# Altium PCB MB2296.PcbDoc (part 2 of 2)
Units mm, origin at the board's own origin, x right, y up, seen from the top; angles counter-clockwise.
Board outline 43 x 47.02 mm, 4 copper layers (Top Layer, Internal 1, Internal 2, Bottom Layer), stack 1.565 mm thick; 91 components, 90 nets, 355 pads, 438 vias.
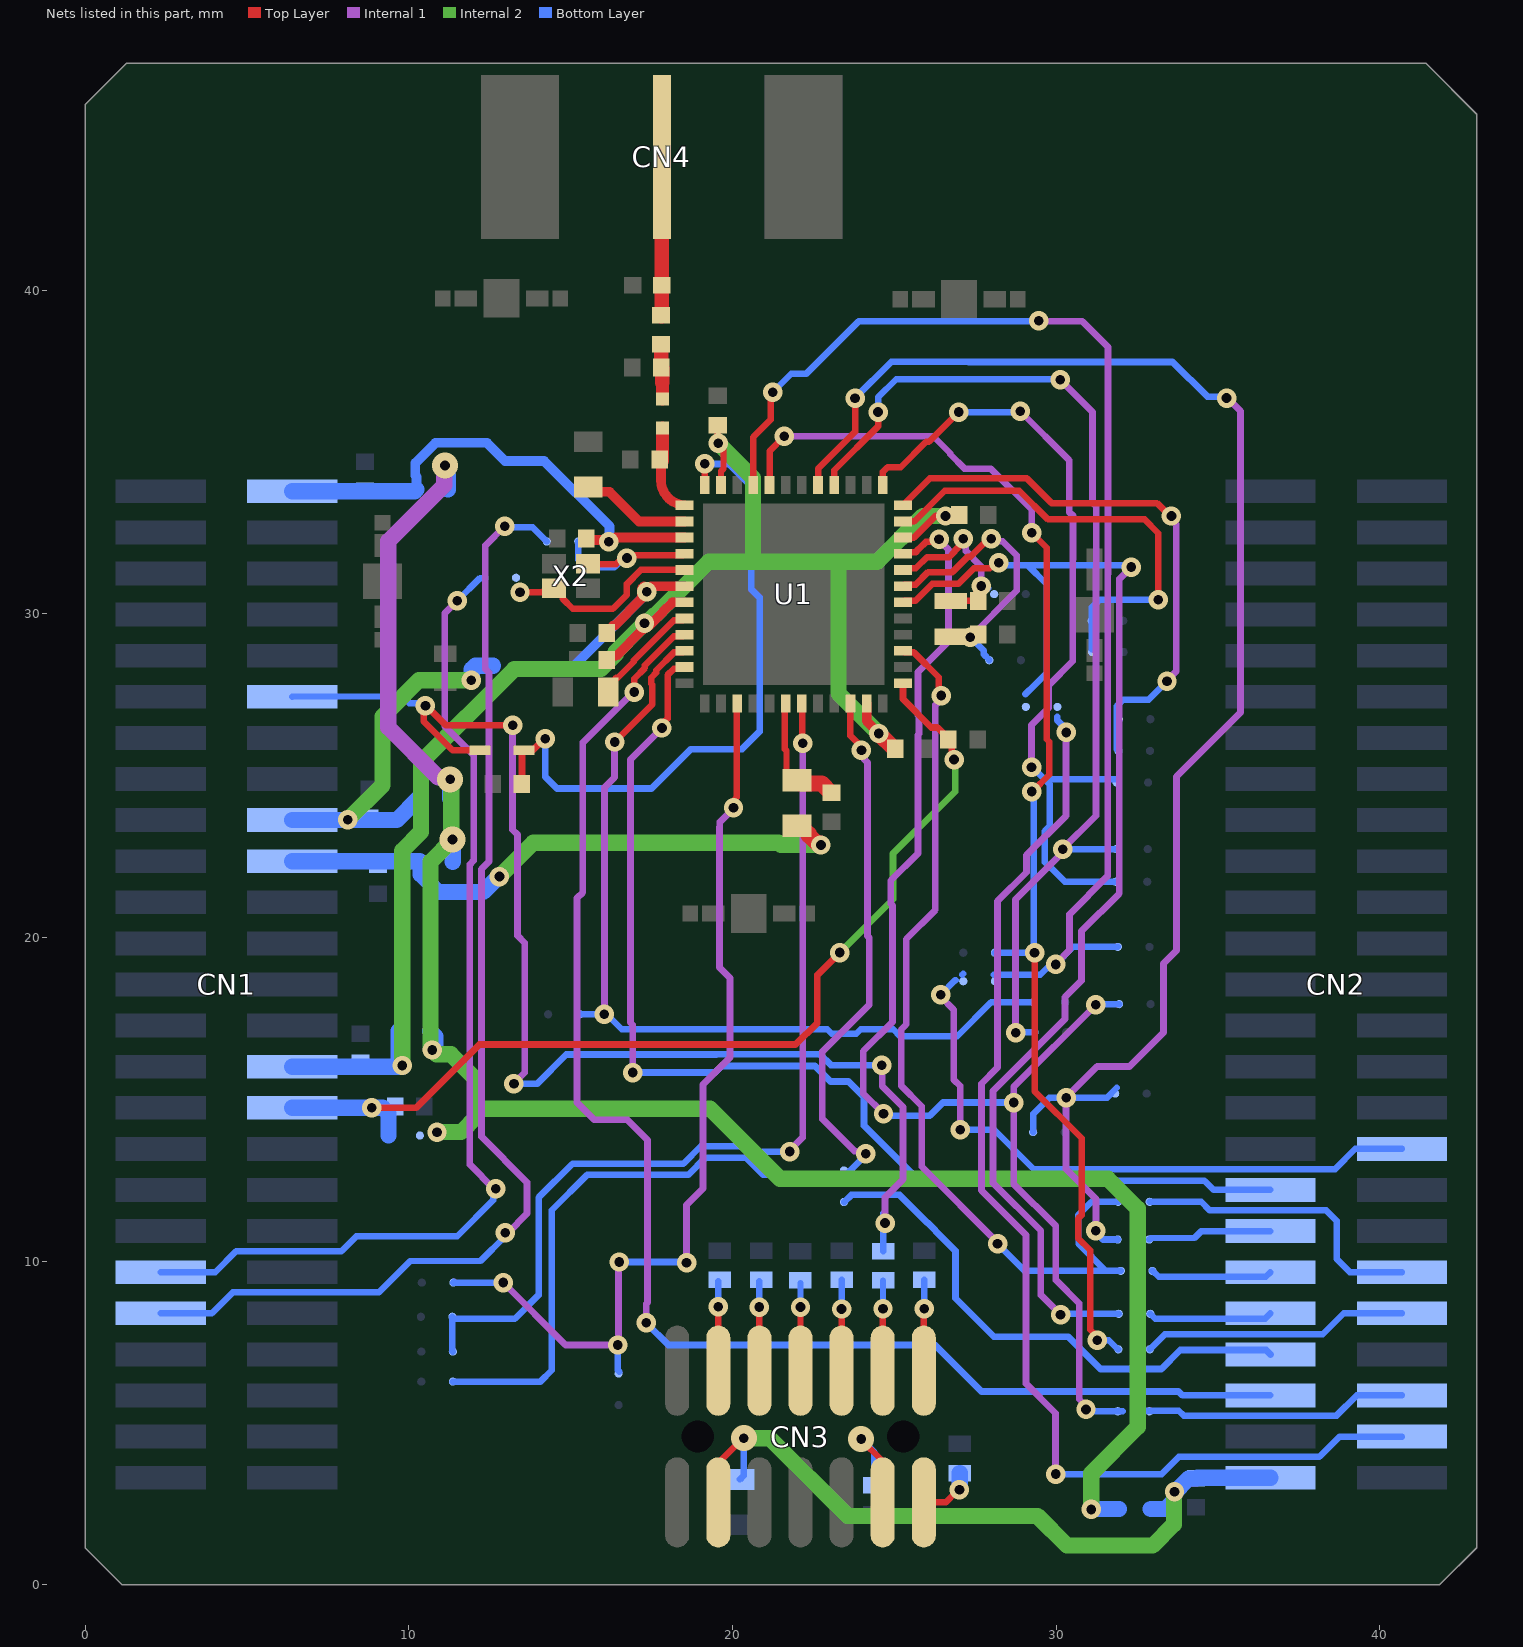
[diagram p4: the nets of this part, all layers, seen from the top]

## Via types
v1: diameter 0.6, hole 0.3, Top Layer to Bottom Layer, tented both sides, 433 vias
v2: diameter 0.8, hole 0.3, Top Layer to Bottom Layer, tented both sides, 5 vias

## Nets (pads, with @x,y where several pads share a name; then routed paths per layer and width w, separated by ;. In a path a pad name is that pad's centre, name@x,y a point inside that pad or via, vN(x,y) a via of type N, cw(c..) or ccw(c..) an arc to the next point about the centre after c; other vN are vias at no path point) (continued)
GPIO46: CN2.34 SB32.2 | length 19.6
  Internal 1 w0.21: v1(26.436,18.235) 26.436,18.17 26.835,17.771 26.835,15.612 27.039,15.408 v1(27.039,14.062)
  Bottom Layer w0.2: v1(26.436,18.235) 26.886,18.685 26.894,18.685 ; v1@27.039,14.163 v1(27.039,14.062) 28.086,14.062 29.305,12.843 38.621,12.843 39.246,13.468 CN2.34@40.688,13.468 ; 27.094,18.845 27.13,18.88
GPIO47: CN2.35 U1.47 | length 35.3
  Top Layer w0.2: v1(17.82,26.474) 17.82,26.582 17.995,26.757 17.995,28.112 18.191,28.308 18.47,28.308 U1.47@18.52,28.358
  Internal 1 w0.21: v1(16.916,15.826) 16.916,17.304 16.845,17.375 16.845,25.499 v1(17.82,26.474)
  Bottom Layer w0.2: 27.586,12.487 34.582,12.487 34.871,12.198 CN2.35@36.624,12.198
  Bottom Layer w0.21: v1(16.916,15.826) 19.463,15.826 19.668,16.031 22.553,16.031 23.033,15.55 23.581,15.55 24.061,15.07 24.061,14.184 25.758,12.487 27.586,12.487
GPIO49: CN2.37 SB29.1 | length 3.9
  Bottom Layer w0.2: SB29.1@32.877,10.668 32.892,10.668 32.938,10.715 34.276,10.715 34.49,10.928 CN2.37@36.624,10.928
GPIO50: CN2.39 SB12.1 | length 3.8
  Bottom Layer w0.2: SB12.1@32.975,9.698 32.99,9.698 33.173,9.514 36.48,9.514 CN2.39@36.624,9.658
GPIO51: CN2.40 SB15.2 | length 9.4
  Bottom Layer w0.2: SB15.2@32.889,11.832 34.481,11.832 34.741,11.573 38.342,11.573 38.672,11.243 38.672,10.066 39.08,9.658 CN2.40@40.688,9.658
GPIO52: CN2.41 SB16.2 | length 3.8
  Bottom Layer w0.2: SB16.2@32.91,8.371 33.061,8.22 36.456,8.22 CN2.41@36.624,8.388
GPIO53: CN2.42 SB18.2 | length 8.3
  Bottom Layer w0.2: SB18.2@32.898,7.274 33.362,7.738 38.24,7.738 38.891,8.388 CN2.42@40.688,8.388
GPIO54: CN2.43 SB8.1 | length 16.7
  Bottom Layer w0.21: SB8.1@23.454,11.827 23.676,12.048 24.305,12.048 25.158,12.048 26.01,11.195 26.021,11.195 26.527,10.688 26.527,10.678 26.887,10.318 26.887,8.852 28.074,7.666 30.374,7.666 31.374,6.666 33.251,6.666 33.836,7.251 36.492,7.251 CN2.43@36.624,7.118
GPIO55: CN2.45 U1.45 | length 44.6
  Top Layer w0.2: v1(16.967,27.584) 16.963,27.589 16.963,27.999 17.295,28.331 17.295,28.412 18.191,29.308 18.47,29.308 U1.45@18.52,29.358
  Internal 1 w0.21: v1(16.967,27.584) 16.935,27.584 15.374,26.023 15.374,21.397 15.196,21.219 15.196,14.906 15.736,14.367 16.753,14.367 17.374,13.747 17.374,8.718 17.336,8.68 v1(17.336,8.093)
  Bottom Layer w0.2: 33.782,5.972 33.906,5.848 CN2.45@36.624,5.848
  Bottom Layer w0.21: v1(17.336,8.093) 18.016,7.413 26.253,7.413 27.694,5.972 33.782,5.972
GPIO56: CN2.46 SB34.2 | length 8.4
  Bottom Layer w0.2: 32.655,5.377 32.885,5.377 32.892,5.37 32.91,5.37 32.917,5.377 33.79,5.377 33.941,5.226 38.667,5.226 39.289,5.848 CN2.46@40.688,5.848
GPIO57: CN2.48 SB42.2 | length 36.7
  Internal 1 w0.21: v1(29.985,3.42) 29.985,5.299 29.071,6.214 29.071,10.811 27.694,12.188 27.694,15.482 28.191,15.979 28.191,21.123 29.085,22.016 29.085,22.543 30.302,23.761 30.302,26.329 v1(30.31,26.337)
  Bottom Layer w0.2: v1(29.985,3.42) 33.262,3.42 33.795,3.953 38.138,3.953 38.764,4.578 CN2.48@40.688,4.578
  Bottom Layer w0.21: 30.033,26.823 30.033,26.72 30.31,26.442 v1(30.31,26.337)
NetC7_2: C7.2 D1.1 U1.36 | length 20.8
  Top Layer w0.21: C7.2@13.492,24.745 13.492,25.722 D1.1@13.554,25.784 13.827,25.784 v1@14.212,26.169 ; v1(14.212,26.145) v1@14.212,26.169 ; v1@14.332,26.289 v1@14.212,26.169 ; U1.36@19.145,33.983 v1(19.145,34.636)
  Bottom Layer w0.21: v1(14.212,26.145) 14.212,24.969 14.579,24.602 17.499,24.602 18.717,25.82 20.293,25.82 20.841,26.368 20.841,30.505 20.578,30.768 20.578,33.952 19.894,34.636 v1(19.145,34.636)
NetC8_2: C8.2 SB38.1 U1.19 X1.2 | length 9.4
  Top Layer w0.2: U1.19@25.27,30.858 25.32,30.908 25.661,30.908 26.044,31.292 26.797,31.292 27.277,31.772 27.362,31.772 27.912,32.322 v1(28.001,32.322) ; v1(27.347,29.283) 27.512,29.283 C8.2@27.592,29.362
  Top Layer w0.21: X1.2@26.814,29.295 26.959,29.15 C8.2@27.461,29.15
  Internal 1 w0.2: v1(27.347,29.283) 28.779,30.715 28.779,31.813 28.347,32.245 28.077,32.245 v1(28.001,32.322)
  Bottom Layer w0.2: v1(27.347,29.283) 27.771,28.858 27.771,28.749 27.936,28.583 SB38.1@27.936,28.569
NetC9_2: C9.2 SB37.1 U1.20 X1.1 | length 5.8
  Top Layer w0.2: U1.20@25.27,31.358 25.32,31.408 25.666,31.408 26.011,31.753 26.697,31.753 26.847,31.902 26.847,31.926 27.134,32.214 v1(27.134,32.322) ; X1.1@26.644,30.395 26.648,30.399 C9.2@27.576,30.399 ; C9.2@27.576,30.616 C9.2@27.549,30.643 ; C9.2@27.592,30.404 27.587,30.399 C9.2@27.576,30.399 ; v1(27.686,30.861) 27.549,30.724 C9.2@27.549,30.643 ; C9.2@27.549,30.643 27.549,30.426 C9.2@27.576,30.399
  Internal 1 w0.21: v1(27.134,32.322) 27.209,32.247 27.209,31.948 27.686,31.471 v1(27.686,30.861)
  Bottom Layer w0.2: v1(27.686,30.861) 27.747,30.8 v1@27.899,30.8
NetC11_2: C11.2 U1.38 | length 3.4
  Top Layer w0.3: C11.2@15.545,33.92 15.693,33.772 16.198,33.772 17.112,32.858 U1.38@18.52,32.858
NetC12_2: C12.2 L1.1 U1.37 | length 2.9
  Top Layer w0.2: L1.1@17.785,35.7 L1.1@17.831,35.745 ; C12.2@17.789,34.731 C12.2@17.831,34.731
  Top Layer w0.3: L1.1@17.785,35.7 L1.1@17.789,35.696 ; C12.2@17.789,34.731 17.789,34.131 ccw(c18.563,34.131) U1.37@18.52,33.358
  Top Layer w0.4: C12.2@17.831,34.731 L1.1@17.831,35.745
NetC13_2: C13.2 L1.2 L2.1 | length 1.7
  Top Layer w0.4: L1.2@17.831,36.645 17.831,37.15
  Top Layer w0.45: L2.1@17.797,38.325 C13.2@17.798,37.617 17.828,37.587 17.828,37.371 17.831,37.368 17.831,37.15
NetC14_2: C14.2 CN4.1 L2.2 | length 4.9
  Top Layer w0.45: L2.2@17.796,39.226 L2.2@17.808,39.237 ; L2.2@17.811,39.231 C14.2@17.811,40.152 ; C14.2@17.816,40.157 CN4.1@17.816,44.118
  Top Layer w0.5: L2.2@17.808,39.231 L2.2@17.811,39.231 ; C14.2@17.811,40.152 C14.2@17.816,40.157 ; CN4.1@17.816,44.118 CN4.1@17.819,44.12
NetC15_1: C15.1 SB6.2 U1.42 | length 8
  Top Layer w0.3: C15.1@16.123,29.444 16.318,29.639 16.362,29.639 17.193,30.469 17.193,30.781 17.264,30.853 17.346,30.772 17.389,30.772 17.475,30.858 U1.42@18.52,30.858
  Bottom Layer w0.3: SB6.2@13.571,28.401 15.114,28.401 17.348,30.635 v1(17.348,30.683)
NetC20_2: C20.2 L3.2 U1.6 | length 3.8
  Top Layer w0.2: U1.6@21.645,27.233 21.619,27.207 21.619,25.821 21.669,25.771 21.669,25.109 21.919,24.859 L3.2@21.995,24.859
  Top Layer w0.5: L3.2@21.995,24.859 22.095,24.759 22.758,24.759 23.038,24.478 C20.2@23.063,24.478
NetC29_1: C29.1 U1.44 | length 3.4
  Top Layer w0.2: C29.1@16.159,27.586 16.164,27.581 16.359,27.776 16.359,27.978 16.402,28.021 16.442,28.021 16.466,28.045 16.945,28.524 16.945,28.562 18.191,29.808 18.47,29.808 U1.44@18.52,29.858
NetCN3_4: CN3.4 R2.1 | length 2.8
  Top Layer w0.2: CN3.4@19.561,6.614 v1(19.561,8.589) v1@19.561,8.639
  Bottom Layer w0.2: v1(19.561,8.589) R2.1@19.561,9.384
NetCN3_6: CN3.6 R3.1 | length 2.8
  Top Layer w0.2: CN3.6@20.831,6.614 v1(20.831,8.579)
  Bottom Layer w0.2: v1(20.831,8.579) R3.1@20.831,9.372
NetCN3_8: CN3.8 R4.1 | length 2.7
  Top Layer w0.2: CN3.8@22.101,6.614 v1(22.101,8.579)
  Bottom Layer w0.2: v1(22.101,8.579) R4.1@22.101,9.31
NetCN3_10: CN3.10 R5.1 | length 2.8
  Top Layer w0.2: CN3.10@23.371,6.614 v1(23.371,8.519)
  Bottom Layer w0.2: v1(23.371,8.519) R5.1@23.371,9.423
NetCN3_11: CN3.11 R6.2 | length 3.9
  Top Layer w0.2: v2(23.976,4.504) 23.951,4.504 24.641,3.814 CN3.11@24.641,2.544
  Bottom Layer w0.2: v2(23.976,4.504) 24.386,4.094 R6.2@24.386,3.081
NetCN3_12: CN3.12 R7.1 | length 2.8
  Top Layer w0.2: CN3.12@24.641,6.614 24.641,8.519 v1(24.651,8.529)
  Bottom Layer w0.2: v1(24.651,8.529) R7.1@24.651,9.396
NetCN3_13: CN3.13 R9.2 | length 1.6
  Top Layer w0.2: CN3.13@25.911,2.544 26.591,2.544 v1@26.901,2.854
  Bottom Layer w0.5: v1@27.024,2.947 R9.2@27.024,3.45
  other v1: 27.013,2.937
NetCN3_14: CN3.14 R8.1 | length 2.8
  Top Layer w0.2: CN3.14@25.911,6.614 25.911,8.539 25.921,8.529 v1(25.926,8.529)
  Bottom Layer w0.2: v1(25.926,8.529) R8.1@25.926,9.424
NetSB1_1: SB1.1 SB2.1 SB3.1 SB4.1 SB5.1 SB43.1 | length 59.6
  Internal 1 w0.5: v2(11.115,34.585) 11.093,34.563 11.093,33.981 9.36,32.249 9.36,26.494 10.909,24.945 11.218,24.945 v2(11.275,24.888)
  Internal 2 w0.5: v1(10.87,13.983) 10.875,13.988 11.612,13.988 12.102,14.477 12.102,14.709 ; v2(11.275,24.888) 11.312,24.852 11.312,23.072 v2@11.352,23.032 ; v2(11.348,23.028) 11.348,23.022 10.671,22.344 10.671,16.573 10.852,16.391 11.299,16.391 12.102,15.589 12.102,14.709 ; v1(31.087,2.327) 31.087,3.439 32.525,4.877 32.525,11.624 31.601,12.548 21.468,12.548 19.307,14.709 12.102,14.709
  Bottom Layer w0.5: SB4.1@10.651,17.107 10.814,16.945 10.814,16.591 10.745,16.523 v1(10.721,16.523) ; v2(11.115,34.585) 11.172,34.528 11.172,34.316 11.214,34.274 SB2.1@11.214,33.846 ; SB3.1@11.269,24.295 11.269,24.882 v2(11.275,24.888) ; v2(11.348,23.028) 11.355,23.022 SB1.1@11.355,22.342 ; v1(31.087,2.327) 31.103,2.343 SB5.1@31.947,2.343
NetSB7_1: SB7.1 SB11.1 U1.24 | length 17.7
  Top Layer w0.2: U1.24@25.27,33.358 26.099,34.187 29.098,34.187 29.859,33.426 33.116,33.426 33.517,33.025 v1(33.563,33.025)
  Internal 1 w0.21: v1(33.426,27.915) 33.426,27.944 33.715,28.233 33.715,32.768 33.563,32.919 v1(33.563,33.025)
  Bottom Layer w0.2: SB11.1@31.878,26.746 31.878,25.817 SB7.1@31.928,25.767 ; SB11.1@31.914,26.746 31.929,26.76 31.929,26.771 31.878,26.821 31.878,27.151 32.073,27.346 32.858,27.346 v1(33.426,27.915)
NetSB8_2: SB8.2 SB9.2 U1.10 | length 34.5
  Top Layer w0.2: U1.10@23.645,27.233 23.645,26.232 23.985,25.891 v1(23.985,25.783)
  Internal 1 w0.21: 23.673,17.377 22.776,16.48 22.776,14.391 23.77,13.397 23.942,13.397 24.025,13.314 v1@24.025,13.265 ; 23.674,17.377 24.228,17.931 24.228,19.991 24.17,20.048 24.17,25.406 24.06,25.516 24.06,25.709 v1(23.985,25.783)
  Bottom Layer w0.2: SB9.2@11.359,6.277 14.067,6.277 14.415,6.625 14.415,11.573 15.505,12.663 18.629,12.663 19.165,13.199 20.421,13.199 20.957,12.663 23.496,12.663 24.155,13.322 v1(24.122,13.322)
NetSB10_1: SB10.1 SB13.1 U1.23 | length 14.3
  Top Layer w0.2: U1.23@25.27,32.858 25.613,32.858 26.56,33.805 28.865,33.805 29.751,32.92 32.736,32.92 33.16,32.496 v1(33.16,30.437)
  Bottom Layer w0.2: SB10.1@31.102,28.905 31.102,29.7 31.105,29.704 31.105,30.2 31.343,30.437 v1(33.16,30.437)
NetSB12_2: SB12.2 SB15.1 U1.15 | length 28.4
  Top Layer w0.2: U1.15@25.27,28.858 25.32,28.808 25.607,28.808 26.377,28.039 26.377,27.553 v1(26.453,27.476)
  Internal 1 w0.2: v1(26.453,27.476) 26.453,27.368 26.271,27.186 26.271,20.852 25.37,19.951 25.37,17.313 25.21,17.152 25.21,15.425 25.846,14.789 25.846,12.922 28.191,10.577 v1(28.191,10.541)
  Bottom Layer w0.2: v1(28.191,10.541) 29.034,9.698 31.538,9.698 ; SB15.1@31.914,11.832 31.095,11.832 30.68,11.417 30.68,10.71 30.693,10.697 30.693,10.542 31.538,9.698 ; SB12.2@32,9.698 31.538,9.698
NetSB14_2: SB14.2 SB17.2 U1.7 | length 29.6
  Top Layer w0.21: U1.7@22.145,27.233 22.157,27.221 22.157,26.012 v1(22.169,26)
  Internal 1 w0.21: v1(21.768,13.386) 21.768,13.417 22.169,13.818 v1(22.169,26)
  Bottom Layer w0.2: SB17.2@11.345,8.28 11.339,8.274 SB17.2@11.339,8.221 ; SB14.2@11.359,7.205 11.339,7.224 SB17.2@11.339,8.221 ; v1(21.768,13.386) 20.729,13.386 20.566,13.549 19.02,13.549 18.484,13.013 15.057,13.013 14.008,11.964 14.008,8.952 13.278,8.221 SB17.2@11.339,8.221
NetSB16_1: SB16.1 SB42.1 U1.18 | length 39.4
  Top Layer w0.2: U1.18@25.27,30.358 25.32,30.408 25.656,30.408 26.174,30.926 26.973,30.926 27.46,31.413 27.949,31.413 28.121,31.585 v1(28.229,31.585)
  Internal 1 w0.21: v1(30.137,8.347) 29.528,8.957 29.528,10.938 28.054,12.412 28.054,15.256 30.277,17.48 30.277,18.156 30.788,18.666 30.788,20.199 31.955,21.366 31.955,31.08 v1(32.322,31.447)
  Bottom Layer w0.2: v1(28.229,31.585) 28.305,31.51 29.118,31.51 ; 29.325,27.79 29.709,28.175 29.709,30.918 29.118,31.51 ; v1@30.417,8.371 SB16.1@31.935,8.371 ; v1(32.322,31.447) 32.259,31.51 29.118,31.51
  Bottom Layer w0.21: 29.058,27.523 29.325,27.79
NetSB18_1: SB18.1 SB20.1 U1.32 | length 39.4
  Top Layer w0.2: U1.32@21.145,33.983 21.145,35.03 v1(21.602,35.487) ; v1(29.245,32.508) 29.709,32.044 29.709,26.129 29.791,26.047 29.791,25.032 29.269,24.509 v1(29.248,24.509) ; v1(29.335,19.531) 29.335,15.25 30.789,13.795 30.789,11.424 30.68,11.315 30.68,10.71 31.055,10.335 31.055,7.879 31.27,7.663 v1(31.27,7.555)
  Internal 1 w0.2: v1(21.602,35.487) 26.206,35.487 26.728,34.965 26.728,34.931 27.166,34.493 27.976,34.493 29.245,33.224 v1(29.245,32.508)
  Bottom Layer w0.2: SB20.1@28.108,19.531 v1(29.335,19.531) 29.303,19.562 29.303,24.454 v1(29.248,24.509) ; v1(31.27,7.555) 31.628,7.555 31.909,7.274 SB18.1@31.923,7.274
NetSB19_2: SB19.2 SB21.2 U1.3 | length 29.6
  Top Layer w0.2: v1(20.031,24.013) 20.108,24.09 20.108,24.305 20.133,24.33 20.133,27.221 U1.3@20.145,27.233
  Internal 1 w0.21: v1(12.916,9.338) 14.847,7.407 v1(16.452,7.407) 16.476,7.431 16.476,9.951 v1(16.498,9.973) ; v1(18.58,9.947) 18.58,11.736 19.085,12.24 19.085,15.457 19.92,16.293 19.92,18.753 19.598,19.075 19.598,23.41 19.607,23.419 19.607,23.568 20.031,23.992 v1(20.031,24.013)
  Bottom Layer w0.2: SB19.2@11.375,9.337 11.402,9.363 11.427,9.338 v1(12.916,9.338) ; v1(16.452,7.407) 16.452,6.632 SB21.2@16.506,6.578
  Bottom Layer w0.21: v1(16.498,9.973) 18.555,9.973 v1(18.58,9.947)
NetSB22_2: SB22.2 SB24.2 SB29.2 U1.29 | length 49
  Top Layer w0.2: U1.29@22.645,33.983 22.645,34.484 23.787,35.627 v1(23.787,36.668)
  Internal 1 w0.21: v1(31.23,10.938) 31.23,11.92 30.31,12.84 v1(30.31,15.053) 31.27,16.014 32.267,16.014 33.316,17.063 33.316,19.197 33.719,19.599 33.719,24.97 35.7,26.951 35.7,36.264 35.295,36.669 v1(35.269,36.669)
  Bottom Layer w0.2: v1(23.787,36.668) 24.906,37.787 27.29,37.787 ; SB22.2@29.291,13.988 29.291,14.549 29.794,15.053 v1(30.31,15.053) 31.574,15.053 31.876,15.354
  Bottom Layer w0.21: 27.29,37.787 33.599,37.787 34.673,36.713 35.225,36.713 v1(35.269,36.669) ; v1(31.23,10.938) 31.2,10.938 31.19,10.928 31.451,10.668 SB29.2@31.902,10.668
NetSB26_2: SB26.2 SB27.2 U1.28 | length 33.1
  Top Layer w0.2: U1.28@23.145,33.983 23.145,34.438 24.499,35.792 v1(24.499,36.236)
  Internal 1 w0.21: v1(28.749,17.053) 28.749,21.171 30.203,22.626 v1(30.203,22.731) 31.235,23.762 31.235,31.378 31.24,31.383 31.24,33.334 31.126,33.449 31.126,36.236 30.129,37.232 v1(30.125,37.232)
  Bottom Layer w0.2: v1(24.499,36.236) 24.499,36.694 25.057,37.252 30.105,37.252 v1(30.125,37.232) ; v1(28.749,17.053) 28.772,17.075 SB27.2@29.335,17.075 ; v1(30.203,22.731) SB26.2@31.858,22.731
NetSB28_2: SB28.2 SB30.2 U1.46 | length 27.3
  Top Layer w0.2: v1(16.358,26.041) 17.517,27.2 17.517,27.812 17.486,27.844 17.486,28.027 17.645,28.186 17.645,28.262 18.191,28.808 18.47,28.808 U1.46@18.52,28.858
  Internal 1 w0.21: v1@16.049,17.639 16.049,24.642 16.358,24.95 v1(16.358,26.041)
  Bottom Layer w0.2: v1(16.037,17.628) 16.118,17.628 16.581,17.165 22.925,17.165 23.067,17.022 23.821,17.022 23.964,17.165 24.964,17.165 25.178,16.951 26.943,16.951 27.992,18 SB28.2@29.307,18
  Bottom Layer w0.21: SB30.2@15.279,17.628 v1(16.037,17.628)
NetSB31_1: SB31.1 SB32.1 U1.33 | length 38.7
  Top Layer w0.2: U1.33@20.645,33.983 20.645,35.465 21.185,36.005 21.185,36.783 v1(21.247,36.846)
  Internal 1 w0.21: v1(29.464,39.062) 29.484,39.042 30.81,39.042 31.6,38.252 31.6,31.234 31.595,31.229 31.595,21.895 30.417,20.717 30.417,19.611 29.991,19.185 v1(29.991,19.168)
  Bottom Layer w0.2: v1(21.247,36.846) 21.758,37.356 21.815,37.414 22.272,37.414 23.634,38.776 ; 28.069,18.845 29.511,18.845 29.833,19.168 v1(29.991,19.168) 30.534,19.71 SB31.1@31.91,19.71
  Bottom Layer w0.21: 23.634,38.776 23.901,39.042 29.444,39.042 v1(29.464,39.062)
NetSB33_2: SB33.2 SB35.2 U1.25 | length 25.5
  Top Layer w0.2: U1.25@24.645,33.983 24.645,34.386 24.793,34.535 25.198,34.535 25.983,35.32 26.072,35.32 v1(26.988,36.236)
  Internal 1 w0.21: v1(28.893,36.262) 30.406,34.749 30.406,33.15 30.52,33.036 30.52,31.681 30.515,31.676 30.515,28.542 29.765,27.793 29.765,27.092 29.241,26.568 v1(29.241,25.259)
  Bottom Layer w0.2: v1(26.988,36.236) v1@28.918,36.236 ; v1(29.241,25.259) 29.275,25.259 29.642,24.893 ; SB35.2@31.842,21.723 30.273,21.723 29.787,22.209 29.771,22.209 29.653,22.326 29.653,23.288 29.798,23.433 29.798,24.737 29.642,24.893 ; SB33.2@31.852,24.893 29.642,24.893
NetSB34_1: SB34.1 SB36.1 U1.21 | length 41.2
  Top Layer w0.21: U1.21@25.27,31.858 25.315,31.903 25.653,31.903 25.753,32.003 25.755,32.003 25.981,32.229 26.31,32.229 v1(26.385,32.303)
  Internal 1 w0.21: v1(24.666,14.556) 24.041,15.18 24.041,16.486 24.948,17.393 24.948,20.993 24.89,21.051 24.89,21.755 25.735,22.599 25.735,26.262 25.766,26.294 25.766,26.837 25.735,26.869 25.735,28.204 26.673,29.143 26.673,31.985 26.385,32.274 v1(26.385,32.303) ; v1(30.925,5.417) 30.925,5.523 30.715,5.732 30.715,8.696 29.992,9.419 29.992,11.084 28.69,12.386 v1(28.69,14.9) 28.69,15.383 v1(31.23,17.923)
  Bottom Layer w0.2: v1(30.925,5.417) 30.983,5.359 SB34.1@31.91,5.359 32.064,5.359 ; v1(31.23,17.923) 31.248,17.941 SB36.1@31.946,17.941
  Bottom Layer w0.21: v1(24.666,14.556) 24.727,14.494 26.099,14.494 26.505,14.9 v1(28.69,14.9)
NetSB39_1: SB39.1 U1.41 X2.1 | length 6.2
  Top Layer w0.2: v1(13.434,30.673) 14.091,30.673 ; X2.1@14.141,30.678 14.364,30.678 X2.1@14.484,30.797 14.559,30.797 14.759,30.597 14.759,30.518 14.761,30.516 14.761,30.462 15.065,30.159 16.306,30.159 16.738,30.59 16.738,30.927 17.169,31.358 U1.41@18.52,31.358
  Bottom Layer w0.2: v1(13.434,30.673) 13.454,30.693 v1@13.476,30.67
NetSB40_1: SB40.1 U1.40 X2.3 | length 5.4
  Top Layer w0.2: X2.3@15.534,31.547 15.543,31.539 16.411,31.539 16.614,31.742 v1@16.722,31.742 ; v1@16.7,31.781 16.727,31.808 18.47,31.808 U1.40@18.52,31.858
  Bottom Layer w0.2: SB40.1@15.235,32.238 15.235,31.674 15.462,31.447 16.353,31.447 16.63,31.725 v1(16.739,31.725)
NRST: CN1.12 D1.2 R7.2 | length 39.6
  Top Layer w0.2: v1(10.512,27.164) 10.453,27.106 10.453,26.682 11.351,25.784 D1.2@12.204,25.784
  Top Layer w0.21: v1(10.512,27.164) 10.532,27.164 11.137,26.56 v1(13.206,26.56)
  Internal 1 w0.21: v1(13.206,26.56) 13.206,23.329 13.353,23.183 13.353,20.057 13.581,19.829 13.581,15.832 v1@13.246,15.497 ; v1(24.611,16.055) 24.626,16.04 24.626,15.408 25.271,14.763 25.271,12.529 24.714,11.972 v1(24.714,11.176)
  Bottom Layer w0.2: CN1.12@6.398,27.438 6.408,27.448 9.812,27.448 10.019,27.241 10.435,27.241 v1(10.512,27.164) ; R7.2@24.658,10.303 24.658,11.479
  Bottom Layer w0.21: v1(13.246,15.478) 13.96,15.478 14.863,16.381 19.509,16.381 19.519,16.391 22.702,16.391 23.037,16.055 v1(24.611,16.055)
OSC_IN: CN1.39 SB39.2 | length 31.8
  Internal 1 w0.21: v1(11.498,30.404) 11.106,30.011 11.106,26.537 12.003,25.639 12.003,22.382 11.883,22.261 11.883,12.987 12.637,12.233 v1(12.688,12.233)
  Bottom Layer w0.2: CN1.39@2.334,9.658 4.017,9.658 4.661,10.302 7.916,10.302 8.381,10.767 11.491,10.767 12.611,11.888 12.611,12.157 v1(12.688,12.233) ; v1(11.498,30.404) 12.201,31.106 12.326,31.106 SB39.2@12.337,31.117
OSC_OUT: CN1.41 SB40.2 | length 36.4
  Internal 1 w0.21: v1(12.962,32.708) 12.363,32.109 12.363,28.299 12.48,28.182 12.48,22.349 12.243,22.112 12.243,13.846 13.653,12.437 13.653,11.471 13.057,10.875 v1(12.978,10.875)
  Bottom Layer w0.2: CN1.41@2.334,8.388 3.915,8.388 4.56,9.033 9.068,9.033 10.039,10.004 12.211,10.004 12.978,10.771 v1(12.978,10.875) ; v1(12.962,32.708) 12.998,32.672 13.826,32.672 SB40.2@14.26,32.238
VDD1: C2.2 C10.1 CN1.2 SB2.2 U1.39 | length 15.6
  Top Layer w0.3: C10.1@15.478,32.334 15.528,32.283 16.041,32.283 16.084,32.24 v1@16.084,32.132 ; v1(16.18,32.233) 16.261,32.233 16.386,32.358 U1.39@18.52,32.358
  Bottom Layer w0.3: SB2.2@10.239,33.846 10.239,34.235 10.201,34.273 10.201,34.662 10.825,35.285 12.411,35.285 12.969,34.727 14.182,34.727 16.198,32.711 16.198,32.251 v1(16.18,32.233)
  Bottom Layer w0.5: CN1.2@6.398,33.788 10.181,33.788 SB2.2@10.239,33.846
VDD3: C3.2 CN1.18 SB3.2 SB6.1 | length 12.1
  Internal 2 w0.5: v1(8.116,23.638) 9.185,24.707 9.185,26.827 10.309,27.952 v1(11.925,27.952)
  Bottom Layer w0.5: CN1.18@6.398,23.628 9.627,23.628 SB3.2@10.294,24.295 ; v1(11.925,27.952) 11.944,27.971 11.944,28.289 12.056,28.401 SB6.1@12.596,28.401
VDD4: C4.2 C16.1 C17.1 C18.1 C19.1 CN1.30 SB4.2 U1.11 U1.22 U1.35 U1.43 | length 51.7
  Top Layer w0.2: v1@19.546,35.287 C18.1@19.546,35.837 ; v1(19.561,35.271) 19.722,35.111 19.722,34.482 19.645,34.405 U1.35@19.645,33.983 ; U1.22@25.27,32.358 25.608,32.358 26.277,33.026
  Top Layer w0.3: C19.1@16.108,28.575 16.108,28.6 16.213,28.705 16.412,28.705 17.224,29.518 17.224,29.652 v1(17.282,29.71) ; v1@17.377,29.614 17.399,29.614 17.85,30.066 17.85,30.068 18.14,30.358 U1.43@18.52,30.358 ; U1.11@24.145,27.233 24.145,26.684 v1(24.524,26.305)
  Top Layer w0.5: v1(24.524,26.305) 24.998,25.831 C16.1@25.024,25.831 ; v1@26.581,33.026 v1(26.583,33.026) ; v1(26.583,33.026) v1(26.583,33.026) ; v1@26.596,33.011 v1(26.583,33.026)
  Internal 2 w0.5: v1(9.795,16.046) 9.795,22.683 10.375,23.263 10.375,25.412 13.258,28.295 15.933,28.295 16.395,28.758 16.395,28.823 v1(17.282,29.71) ; v1@17.301,29.671 17.309,29.671 17.621,29.983 17.638,29.983 19.269,31.614 20.638,31.614 ; v1(19.561,35.271) 20.638,34.195 20.638,31.614 ; v1(24.524,26.305) 24.519,26.305 23.272,27.552 23.272,31.614 ; v1(26.583,33.026) 25.981,33.026 25.934,32.979 25.886,33.026 24.473,31.614 23.272,31.614 ; 20.638,31.614 23.272,31.614
  Bottom Layer w0.5: CN1.30@6.398,16.008 v1@9.795,16.008 ; SB4.2@9.676,17.107 9.676,16.165 v1(9.795,16.046)
VDD5: C27.2 C28.1 CN1.32 SB43.2 U1.13 | length 31.6
  Top Layer w0.2: C28.1@26.673,26.124 26.77,26.027 26.77,25.576 v1(26.847,25.499)
  Top Layer w0.21: v1(8.852,14.738) 10.223,14.738 12.177,16.692 21.951,16.692 22.622,17.362 22.622,18.84 v1(23.317,19.535) ; U1.13@25.27,27.858 25.27,27.366 26.142,26.494 26.328,26.494 26.673,26.149 C28.1@26.673,26.124
  Internal 2 w0.21: v1(23.317,19.535) 24.964,21.183 24.964,22.597 26.883,24.516 26.883,25.463 v1(26.847,25.499)
  Bottom Layer w0.5: CN1.32@6.398,14.738 v1@8.825,14.738 ; v1(8.852,14.738) 9.194,14.738 9.366,14.566 SB43.2@9.366,13.88
VDD14: C5.2 C22.2 CN2.49 CN3.3 SB5.2 | length 23.9
  Top Layer w0.2: CN3.3@19.561,2.544 19.561,3.764 20.326,4.529 v2(20.351,4.529)
  Internal 2 w0.5: v2(20.351,4.529) 21.154,4.529 23.559,2.124 29.426,2.124 30.341,1.21 32.984,1.21 33.639,1.865 33.639,2.857 v1(33.658,2.876)
  Bottom Layer w0.2: C22.2@20.231,3.254 20.351,3.375 v2(20.351,4.529)
  Bottom Layer w0.5: SB5.2@32.922,2.343 33.388,2.343 33.639,2.594 33.639,2.857 v1(33.658,2.876) ; v1@33.645,2.83 33.645,2.836 34.095,3.286 34.345,3.286 C5.2@34.355,3.296 ; C5.2@34.37,3.308 CN2.49@36.624,3.308
VDDA: C1.2 CN1.20 L3.1 SB1.2 | length 18.6
  Top Layer w0.5: L3.1@21.995,23.459 22.095,23.459 22.358,23.196 22.358,23.158 22.592,22.923 22.643,22.923 22.706,22.86 v1(22.733,22.86)
  Internal 2 w0.5: v1(12.798,21.882) 13.846,22.93 21.424,22.93 21.494,22.86 v1(22.733,22.86)
  Bottom Layer w0.5: CN1.20@6.398,22.358 10.339,22.358 SB1.2@10.368,22.329 10.368,21.949 10.912,21.405 12.293,21.405 12.771,21.882 v1(12.798,21.882)
pads on no net: CN1.3 CN1.4 CN1.5 CN1.10 CN1.11 CN1.16 CN1.19 CN1.21 CN1.23 CN1.27 CN1.43 CN1.48 CN1.50 CN2.1 CN2.3 CN2.4 CN2.6 CN2.17 CN2.19 CN2.31 CN2.33 CN2.36 CN2.47 CN3.1 CN3.2 CN3.9 CN3.NPTH1 CN3.NPTH2 U1.2 U1.48

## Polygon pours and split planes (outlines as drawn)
GND on Bottom Layer "Bottom Layer-GND" (solid, remove dead copper, pour order 7): -2.921,48.419 44.602,48.419 44.602,-0.051 -2.921,-0.051
GND on Internal 2 "Internal 2-GND" (solid, remove dead copper, pour order 11): -4.826,47.467 47.168,47.467 47.168,-0.254 -4.826,-0.254 -4.826,41.605
GND on Internal 1 "Internal 1-GND" (solid, remove dead copper, pour order 13): -2.692,47.93 15.646,47.93 15.646,32.89 19.863,32.89 19.863,47.93 44.78,47.93 44.78,-0.688 -2.692,-0.688
GND on Top Layer "GND_L01_P018" (solid, remove dead copper, pour order 18): -1.947,47.498 46.012,47.498 46.012,-0.483 -1.968,-0.483 -1.968,47.498

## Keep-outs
Top Layer:
  rectangle: 17.532,38.711 18.078,38.814
Keep-Out Layer:
  lines w0.1: 0,45.263 0,39.878 0,1.139 1.139,0 41.852,0 42.504,0.647 43.001,1.141 ; 0.003,45.265 0.003,45.682 1.321,47 41.443,47 43,45.443 43,39.982 43,1.141

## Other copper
Top Layer:
  region: 17.908,36.148 cw(c17.836,36.148) 17.836,36.076 17.786,36.076 cw(c17.786,36.147) 17.715,36.147
  region: 17.714,36.25 cw(c17.786,36.25) 17.786,36.322 17.837,36.322 cw(c17.837,36.251) 17.907,36.251
  region net GND: 17.394,36.278 17.394,36.118 18.195,36.118 18.195,36.278
  pour cut-out: 17.425,37.153 17.425,35.263 18.195,35.263 18.195,37.153 17.429,37.153
  region net NetC12_2: 18.061,33.355 18.207,33.208 18.255,33.208 18.255,33.253 18.153,33.355
  text ".Layer_Name" at 10.118,-41.691 h3
  text ".GTL" at 51.813,-41.691 h3
Internal 1:
  text ".Layer_Name" at 10.118,-41.691 h3
  text ".G1" at 51.813,-41.691 h3
Internal 2:
  text ".Layer_Name" at 10.118,-41.691 h3
  text ".G2" at 51.813,-41.691 h3
Bottom Layer:
  text ".GBL" at 40.609,-41.723 h3
  text ".Layer_Name" at 81.923,-41.723 h3

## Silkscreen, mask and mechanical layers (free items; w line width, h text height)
Top Overlay:
  lines w0.05: -0.592,0 1.139,0 ; 0,-0.5 0,1.139
  lines w0.1: 18.256,34.78 18.431,34.872 19.165,37.27 ; 9.182,20.742 31.182,20.742 31.182,39.742 9.182,39.742 9.182,20.742
  text "L" at 1.959,36.409 h7.62
  text "J" at 2.769,4.644 h8
  text "MB2296A" at 2.769,1.988 h2.5
  text ".Layer_Name" at 10.118,-41.691 h3
  text ".GTO" at 51.813,-41.691 h3
Bottom Overlay:
  lines w0.2: 33.246,18.025 33.897,18.025 ; 33.246,26.389 33.897,26.389
  text "F" at 5.479,41.733 h8
  text "H" at 10.782,41.733 h7.62
  text "I" at 40.141,41.285 h7.62
  text "J" at 29.288,41.237 h8
  text "C" at 35.232,41.072 h7.62
  text "E" at 5.928,37.203 h8
  text "G" at 40.141,36.256 h8
  text ".GBO" at 40.609,-41.723 h3
  text ".Layer_Name" at 81.923,-41.723 h3
Top Paste:
  text ".Layer_Name" at 10.118,-41.691 h3
  text ".GTP" at 51.813,-41.691 h3
Bottom Paste:
  text ".GBP" at 40.609,-41.723 h3
  text ".Layer_Name" at 81.923,-41.723 h3
Top Solder:
  circle w0.254: c17.323,35.619 r0.038
  circle w0.254: c17.323,36.196 r0.038
  circle w0.254: c17.323,36.773 r0.038
  region: 17.605,36.831 cw(c17.805,36.831) 17.805,37.031 17.857,37.031 cw(c17.857,36.833) 18.055,36.831
  region: 18.054,35.631 cw(c17.856,35.606) 17.856,35.406 17.803,35.406 cw(c17.803,35.603) 17.608,35.631
  region: 17.714,36.25 cw(c17.786,36.25) 17.786,36.322 17.837,36.322 cw(c17.837,36.251) 17.907,36.251
  region: 17.908,36.148 cw(c17.836,36.148) 17.836,36.076 17.786,36.076 cw(c17.786,36.147) 17.715,36.147
  region: 17.581,36.801 17.581,36.645 17.674,36.645 17.674,36.8
  region: 18.195,36.439 18.195,35.933 18.7,35.933 18.7,36.439
  region: 17.37,36.278 17.37,36.118 18.208,36.118 18.208,36.278
  lines w1: 9.182,28.058 9.182,20.742 14.212,20.742 ; 9.182,33.925 9.182,39.742 9.995,39.742 ; 16.584,20.754 17.789,20.739 ; 19.749,39.783 24.219,39.767 ; 23.486,20.742 31.295,20.742 31.295,26.305 ; 30.137,39.792 31.153,39.792 31.153,35.093
  text ".Layer_Name" at 10.118,-41.691 h3
  text ".GTS" at 51.813,-41.691 h3
Bottom Solder:
  text ".GBS" at 40.609,-41.723 h3
  text ".Layer_Name" at 81.923,-41.723 h3
M1-Board Shape:
  lines w0.1: 0,1.139 0,39.878 0,45.686 1.314,47 41.444,47 43,45.444 43,39.982 43.001,1.141 41.852,0 1.139,0 0,1.139
M2-Board Dimensions:
  text ".Layer_Name" at 10.118,-41.691 h3
  text ".GM2" at 51.813,-41.691 h3
M4-Bottom Dimensions:
  lines w0.1: 4.367,-4.11 4.367,34.678 ; 38.646,-4.139 38.646,34.65
  text "CN1/CN2 spacing" at 13.705,-6.883 h1
Top M14-Top Assembly:
  text ".Layer_Name" at 10.118,-41.691 h3
  text ".GM14" at 51.813,-41.691 h3
Bottom M14-Top Assembly:
  text ".GM15" at 40.609,-41.723 h3
  text ".Layer_Name" at 81.923,-41.723 h3
Drill Drawing:
  drawing of 315 lines, arcs and shapes, not listed
  text "Layer" at -0.699,115.405 h1.52
  text "Name" at 9.713,115.405 h1.52
  text "Material" at 33.329,115.405 h1.52
  text "Thickness" at 55.167,115.405 h1.52
  text "Constant" at 71.673,115.405 h1.52
  text "Board Layer Stack" at 86.147,115.405 h1.52
  text "Top Overlay" at 9.713,112.357 h1.52
  text "Top Solder" at 9.713,109.309 h1.52
  text "Solder Resist" at 33.329,109.309 h1.52
  text "0.70mil" at 55.167,109.309 h1.52
  text "4.2" at 71.673,109.309 h1.52
  text "1" at -0.699,106.261 h1.52
  text "Top Layer" at 9.713,106.261 h1.52
  text "1.60mil" at 55.167,106.261 h1.52
  text "Dielectric 1" at 9.713,103.213 h1.52
  text "FR-4" at 33.329,103.213 h1.52
  text "3.00mil" at 55.167,103.213 h1.52
  text "3.7" at 71.673,103.213 h1.52
  text "2" at -0.699,100.165 h1.52
  text "Internal 1" at 9.713,100.165 h1.52
  text "1.20mil" at 55.167,100.165 h1.52
  text "Dielectric 3" at 9.713,97.117 h1.52
  text "50.00mil" at 55.167,97.117 h1.52
  text "4.5" at 71.673,97.117 h1.52
  text "3" at -0.699,94.069 h1.52
  text "Internal 2" at 9.713,94.069 h1.52
  text "1.20mil" at 55.167,94.069 h1.52
  text "Dielectric 2" at 9.713,91.021 h1.52
  text "FR-4" at 33.329,91.021 h1.52
  text "3.00mil" at 55.167,91.021 h1.52
  text "3.7" at 71.673,91.021 h1.52
  text "4" at -0.699,87.973 h1.52
  text "Bottom Layer" at 9.713,87.973 h1.52
  text "1.60mil" at 55.167,87.973 h1.52
  text "Bottom Solder" at 9.713,84.925 h1.52
  text "Solder Resist" at 33.329,84.925 h1.52
  text "0.70mil" at 55.167,84.925 h1.52
  text "4.2" at 71.673,84.925 h1.52
  text "Bottom Overlay" at 9.713,81.877 h1.52
  text "Symbol" at -0.519,73.911 h2.16
  text "Count" at 7.943,73.911 h2.16
  text "Hole Size" at 16.77,73.911 h2.16
  text "Plated" at 32.318,73.911 h2.16
  text "Hole Type" at 39.746,73.911 h2.16
  text "Drill Layer Pair" at 50.561,73.911 h2.16
  text "Via/Pad" at 71.06,73.911 h2.16
  text "Pad Shape" at 79.921,73.911 h2.16
  text "Template" at 91.498,73.911 h2.16
  text "Description" at 105.603,73.911 h2.16
  text "438" at 7.943,70.183 h1.8
  text "11.81mil (0.30mm)" at 16.77,70.183 h1.8
  text "PTH" at 32.318,70.183 h1.8
  text "Round" at 39.746,70.183 h1.8
  text "Top Layer - Bottom Layer" at 50.561,70.183 h1.8
  text "Via" at 71.06,70.183 h1.8
  text "Rounded" at 79.921,70.183 h1.8
  text "(Mixed)" at 91.498,70.183 h1.8
  text "2" at 7.943,66.454 h1.8
  text "39.37mil (1.00mm)" at 16.77,66.454 h1.8
  text "NPTH" at 32.318,66.454 h1.8
  text "Round" at 39.746,66.454 h1.8
  text "Top Layer - Bottom Layer" at 50.561,66.454 h1.8
  text "Pad" at 71.06,66.454 h1.8
  text "Rounded" at 79.921,66.454 h1.8
  text "c0hn100m110p0" at 91.498,66.454 h1.8
  text "440 Total" at 7.943,62.726 h1.8
  text ".Layer_Name" at 10.118,-41.691 h3
  text ".DRL" at 51.813,-41.691 h3
M20-Top Title Box:
  circle w0.254: c88.122,-48.411 r1.3
  region: 73.644,-49.505 62.888,-49.505 63.881,-47.012 71.739,-47.012 72.188,-46.252 74.396,-48.801
  region: 87.647,-41.175 72.12,-41.175 71.426,-42.95 70.215,-44.175 68.818,-42.315 68.818,-40.664 69.961,-39.267 71.397,-38.889 87.647,-38.889
  lines w0.254: 63.881,-47.012 72.673,-47.012 69.607,-43.474 cw(c71.411,-41.53) 71.651,-38.889 88.415,-38.889 87.653,-41.175 ; 67.195,-38.642 cw(c69.621,-39.612) 69.858,-37.01 ; 67.234,-38.609 62.888,-49.505 82.211,-49.505 ccw(c82.459,-46.77) 85.008,-47.79 ; 68.974,-42.544 74.396,-48.801 ; 69.228,-42.544 74.533,-48.665 ; 69.228,-42.29 74.533,-48.411 ; 69.326,-41.175 82.319,-41.175 ; 69.355,-42.163 74.66,-48.284 ; 69.482,-42.036 74.787,-48.157 ; 69.609,-41.909 74.914,-48.03 ; 69.736,-41.782 75.041,-47.903 ; 69.791,-39.83 75.096,-45.951 ; 69.859,-37.01 89.309,-37.01 85.009,-47.788 ; 69.863,-41.655 75.113,-47.714 ; 69.863,-41.401 75.168,-47.522 ; 69.863,-41.147 75.168,-47.268 ; 69.863,-40.258 75.168,-46.379 ; 69.99,-41.02 75.295,-47.141 ; 69.99,-40.639 75.295,-46.76 ; 71.362,-47.025 ccw(c71.467,-46.49) 71.764,-46.033 ; 72.448,-41.162 ccw(c72.422,-41.729) 72.092,-42.191 74.457,-44.92 cw(c72.653,-46.864) 73.386,-49.412 ; 78.729,-49.3 81.619,-40.921 ; 78.952,-49.251 81.821,-40.93 ; 79.079,-49.251 81.948,-40.93 ; 79.333,-49.251 82.202,-40.93 ; 79.587,-49.251 82.456,-40.93 ; 79.841,-49.251 82.71,-40.93 ; 80.095,-49.251 82.964,-40.93 ; 80.349,-49.251 83.218,-40.93 ; 80.603,-49.251 83.472,-40.93 ; 80.857,-49.251 83.726,-40.93 ; 81.065,-49.3 83.955,-40.921 ; 83.955,-41.175 87.647,-41.175 ; 86.979,-41.172 87.741,-38.886 ; 87.145,-41.175 87.907,-38.889 ; 87.399,-41.175 88.161,-38.889
  lines w0.3: 1.118,-48.391 61.118,-48.391 ; 1.118,-43.391 61.118,-43.391 ; 1.118,-38.391 61.118,-38.391 ; 41.118,-53.391 41.118,-38.391 ; 61.118,-53.391 61.118,-33.391 ; 78.729,-49.3 81.065,-49.3 ; 1.118,-53.391 91.118,-53.391 91.118,-33.391 1.118,-33.391 1.118,-53.391
  text "Project: '.Board_Name'" at 2.118,-36.607 h3
  text "Layer:" at 2.118,-41.691 h3
  text "Gerber:" at 42.107,-41.691 h3
  text "Variant: '.VariantName'" at 2.118,-46.691 h3
  text "Ref: '.Board_Reference'" at 42.234,-46.691 h3
  text "R" at 87.614,-49.173 h1.52
  text "Date: '.Board_Document_Date'" at 2.118,-51.691 h3
  text "Rev: '.Board_PCB_Revision'" at 42.177,-51.691 h3
M21-Bottom Title Box:
  circle w0.254: c4.3,-48.411 r1.3
  region: 4.775,-41.175 20.302,-41.175 20.997,-42.95 22.207,-44.175 23.604,-42.315 23.604,-40.664 22.461,-39.267 21.025,-38.889 4.775,-38.889
  region: 18.778,-49.505 29.534,-49.505 28.541,-47.012 20.683,-47.012 20.235,-46.252 18.026,-48.801
  lines w0.254: 4.261,-38.889 5.023,-41.175 ; 4.515,-38.889 5.277,-41.175 ; 4.681,-38.886 5.443,-41.172 ; 4.769,-41.175 4.007,-38.889 20.771,-38.889 cw(c21.012,-41.53) 22.815,-43.474 19.749,-47.012 28.541,-47.012 ; 4.775,-41.175 8.468,-41.175 ; 7.413,-47.788 3.114,-37.01 22.563,-37.01 ; 7.414,-47.79 ccw(c9.963,-46.77) 10.212,-49.505 29.534,-49.505 25.188,-38.61 ; 8.468,-40.921 11.357,-49.3 ; 8.696,-40.93 11.566,-49.251 ; 8.95,-40.93 11.82,-49.251 ; 9.204,-40.93 12.074,-49.251 ; 9.458,-40.93 12.328,-49.251 ; 9.712,-40.93 12.582,-49.251 ; 9.966,-40.93 12.836,-49.251 ; 10.103,-41.175 23.096,-41.175 ; 10.22,-40.93 13.09,-49.251 ; 10.474,-40.93 13.344,-49.251 ; 10.601,-40.93 13.471,-49.251 ; 10.804,-40.921 13.693,-49.3 ; 17.127,-47.141 22.432,-41.02 ; 17.127,-46.76 22.432,-40.639 ; 17.254,-47.522 22.559,-41.401 ; 17.254,-47.268 22.559,-41.147 ; 17.254,-46.379 22.559,-40.258 ; 17.309,-47.714 22.559,-41.655 ; 17.327,-45.951 22.632,-39.83 ; 17.381,-47.903 22.686,-41.782 ; 17.508,-48.03 22.813,-41.909 ; 17.635,-48.157 22.94,-42.036 ; 17.762,-48.284 23.067,-42.163 ; 17.889,-48.665 23.194,-42.544 ; 17.889,-48.411 23.194,-42.29 ; 18.026,-48.801 23.448,-42.544 ; 19.037,-49.412 cw(c19.769,-46.864) 17.966,-44.92 20.33,-42.191 ccw(c20,-41.729) 19.974,-41.162 ; 20.658,-46.033 ccw(c20.956,-46.49) 21.061,-47.025 ; 22.565,-37.01 cw(c22.801,-39.612) 25.227,-38.642
  lines w0.3: 11.357,-49.3 13.693,-49.3 ; 31.118,-53.391 31.118,-33.391 ; 31.118,-48.391 91.118,-48.391 ; 31.118,-43.391 91.118,-43.391 ; 31.118,-38.391 91.118,-38.391 ; 51.118,-53.391 51.118,-38.391 ; 1.118,-53.391 1.118,-33.391 91.118,-33.391 91.118,-53.391 1.118,-53.391
  text "Project: '.Board_Name'" at 89.924,-36.607 h3
  text "Gerber:" at 49.935,-41.691 h3
  text "Layer:" at 89.923,-41.691 h3
  text "Ref: '.Board_Reference'" at 49.935,-46.691 h3
  text "Variant: '.VariantName'" at 89.924,-46.691 h3
  text "R" at 4.808,-49.173 h1.52
  text "Rev: '.Board_PCB_Revision'" at 49.992,-51.691 h3
  text "Date: '.Board_Document_Date'" at 89.924,-51.691 h3

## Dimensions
17.819,44.12 to 43,45.444 on M3-Top Dimensions
0,45.686 to 17.819,44.12 on M3-Top Dimensions
41.852,0 to 22.919,56.385 on M3-Top Dimensions
4.367,-4.11 to 38.646,-4.139 on M4-Bottom Dimensions
1.139,0 to 1.321,47 on M3-Top Dimensions
43,1.141 to 0,1.139 on M3-Top Dimensions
